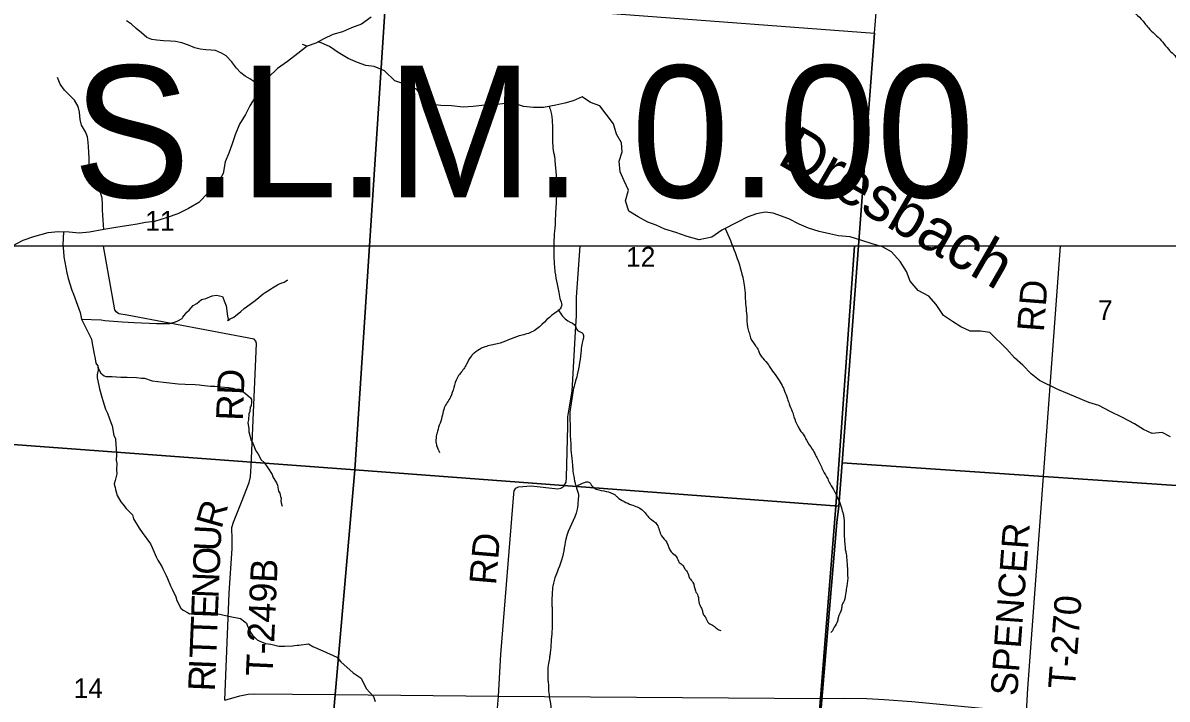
# Model space of a CAD drawing. Extents: x 0 to 42.5, y 0 to 22.
# Drawn here: x 4.279 to 5.494, y 14.597 to 15.314 of the extents above; entities that cross this region are included whole.
import ezdxf

# ---------------------------------------------------------------- set-up
doc = ezdxf.new("R2010")
doc.units = 0
for name, color, linetype in [('GM_X_Interchange_Ramps', 7, 'Continuous'), ('GM_X_Minor_River', 7, 'Continuous'), ('GM_X_Minor_River_Text', 7, 'Continuous'), ('GM_X_Section', 7, 'Continuous'), ('GM_X_Section_Text', 7, 'Continuous'), ('GM_X_State_Route', 7, 'Continuous'), ('GM_X_Township_Road', 7, 'Continuous'), ('GM_X_Township_Road_Text', 7, 'Continuous'), ('SH_Text', 7, 'Continuous')]:
    doc.layers.add(name, color=color, linetype=linetype)

msp = doc.modelspace()

# ---------------------------------------------------------------- linework, layer by layer
at = {"layer": 'GM_X_Interchange_Ramps'}
for points in [[(2.1, 14.1), (5.0849, 14.1), (5.0987, 14.2492), (5.1054, 14.3283), (5.1076, 14.3533), (5.1259, 14.5975), (5.1421, 14.8012), (5.162, 15.0772)], [(5.162, 15.0772), (5.1421, 14.8012), (5.1259, 14.5975), (5.1076, 14.3533), (5.1054, 14.3283), (5.0987, 14.2492), (5.0849, 14.1), (8.0699, 14.1)]]:
    msp.add_lwpolyline(points, dxfattribs=at)
at = {"layer": 'GM_X_Minor_River'}
for points in [[(4.649, 15.3203), (4.6387, 15.3128), (4.6281, 15.3091), (4.6186, 15.3046), (4.6083, 15.3017), (4.5988, 15.2972), (4.5901, 15.2927), (4.581, 15.2894), (4.576, 15.2911)], [(4.5335, 15.2469), (4.5264, 15.2505), (4.5203, 15.2547), (4.5152, 15.2575), (4.5105, 15.2613), (4.5059, 15.2663), (4.5008, 15.2731), (4.4949, 15.2792), (4.4902, 15.2821), (4.4837, 15.2848), (4.479, 15.2853), (4.4735, 15.2857), (4.4674, 15.2863), (4.4617, 15.2878), (4.4549, 15.2905), (4.4479, 15.293), (4.4412, 15.2943), (4.4359, 15.2949), (4.4287, 15.2953), (4.4213, 15.2957), (4.416, 15.2967), (4.411, 15.2986), (4.4051, 15.3037), (4.3995, 15.3081), (4.3945, 15.3129), (4.3894, 15.3165)], [(5.4974, 14.8748), (5.4888, 14.8794), (5.4782, 14.8783), (5.4687, 14.8826), (5.4593, 14.8887), (5.4465, 14.8953), (5.4333, 14.9018), (5.4213, 14.908), (5.4107, 14.9115), (5.388, 14.9208), (5.3779, 14.9251), (5.3583, 14.9347), (5.3496, 14.9416), (5.3406, 14.9508), (5.3319, 14.9588), (5.3237, 14.968), (5.3057, 14.9856), (5.2958, 14.9872), (5.2849, 14.9869), (5.2751, 14.9915), (5.266, 14.9973), (5.2566, 15.0038), (5.2487, 15.0153), (5.2409, 15.0241), (5.2296, 15.0302), (5.2213, 15.0402), (5.2172, 15.0504), (5.2105, 15.0611), (5.2015, 15.0714), (5.1917, 15.0764), (5.1808, 15.0796), (5.1698, 15.0834), (5.1573, 15.087), (5.1449, 15.0882), (5.1354, 15.0902), (5.1245, 15.0929), (5.1131, 15.0964), (5.1033, 15.1007), (5.0924, 15.1061), (5.0758, 15.1123), (5.0671, 15.1135), (5.058, 15.1117), (5.0481, 15.108), (5.0386, 15.1031), (5.0211, 15.0942), (5.0105, 15.0867), (4.9972, 15.0841), (4.9844, 15.0876), (4.9723, 15.0919), (4.9606, 15.0954), (4.9515, 15.0997), (4.9425, 15.1028), (4.9323, 15.1085), (4.9225, 15.1143), (4.9188, 15.1253), (4.9223, 15.1367), (4.9175, 15.1466), (4.9134, 15.1561), (4.9123, 15.1675), (4.9154, 15.1773), (4.9148, 15.1868), (4.9095, 15.196), (4.9062, 15.207), (4.8983, 15.2173), (4.8916, 15.2261), (4.8818, 15.2296), (4.8728, 15.2357), (4.8633, 15.2316), (4.8545, 15.2291), (4.8451, 15.2269), (4.8318, 15.2243), (4.8212, 15.2244), (4.8106, 15.2256), (4.8012, 15.2287), (4.7909, 15.2288), (4.7777, 15.2267), (4.7663, 15.2264), (4.7572, 15.2253), (4.7466, 15.2246), (4.7341, 15.2263), (4.7228, 15.2264), (4.7141, 15.2276), (4.7047, 15.2352), (4.6972, 15.244), (4.6836, 15.2494), (4.6742, 15.2526), (4.6633, 15.2633), (4.652, 15.2679), (4.6433, 15.2691), (4.6346, 15.2722), (4.6244, 15.2765), (4.6138, 15.2826), (4.6048, 15.2892), (4.5958, 15.293), (4.5925, 15.294)], [(4.581, 15.2894), (4.5713, 15.2816), (4.5603, 15.2733), (4.5496, 15.2658), (4.5396, 15.2564), (4.5335, 15.2469), (4.5262, 15.236), (4.52, 15.2261), (4.5154, 15.2171), (4.5092, 15.2068), (4.5046, 15.1955), (4.5019, 15.1868), (4.498, 15.1758), (4.4941, 15.1667), (4.4917, 15.1545), (4.4852, 15.1424), (4.476, 15.1338), (4.4661, 15.1236), (4.455, 15.1172), (4.4439, 15.1116), (4.4325, 15.1075), (4.4188, 15.1034), (4.4093, 15.1024), (4.4006, 15.1005), (4.3918, 15.0991), (4.38, 15.0973), (4.3652, 15.0951), (4.35, 15.0922), (4.339, 15.0912), (4.3283, 15.092), (4.317, 15.0925), (4.3056, 15.0914), (4.2907, 15.087), (4.2793, 15.0833), (4.2679, 15.0773)], [(4.3652, 15.0951), (4.3644, 15.1049), (4.364, 15.11), (4.3638, 15.1157), (4.3636, 15.1216), (4.3633, 15.1282), (4.3616, 15.1343), (4.3555, 15.141), (4.3513, 15.1461), (4.3502, 15.1522), (4.3498, 15.1569), (4.3496, 15.1626), (4.3495, 15.1701), (4.3493, 15.1769), (4.3489, 15.1826), (4.3486, 15.1875), (4.3478, 15.1932), (4.3457, 15.1986), (4.3414, 15.2058), (4.34, 15.2115), (4.3393, 15.2193), (4.338, 15.2256), (4.3342, 15.2322), (4.3236, 15.2429), (4.319, 15.2491), (4.316, 15.2562)], [(4.3222, 15.0923), (4.3218, 15.0787), (4.3225, 15.0718), (4.3228, 15.0658), (4.3258, 15.0488), (4.3273, 15.0429), (4.3311, 15.0304), (4.3329, 15.0264), (4.3401, 15.0069), (4.3414, 14.9999), (4.346, 14.9906), (4.352, 14.9784)], [(4.3414, 14.9999), (4.3625, 14.999), (4.3663, 14.9982), (4.3847, 14.9971), (4.3973, 14.9963), (4.4211, 14.9953), (4.4353, 14.9952), (4.4412, 14.9971), (4.4437, 14.998), (4.4485, 15.0005), (4.449, 15.002), (4.4532, 15.0073), (4.4557, 15.0092), (4.4601, 15.0143), (4.4639, 15.0163), (4.4689, 15.0208), (4.4735, 15.0218), (4.4803, 15.0246), (4.4847, 15.0251), (4.491, 15.0237), (4.4936, 15.0173), (4.4951, 15.0138), (4.4966, 15.0028), (4.497, 14.9999), (4.4979, 14.9984), (4.4966, 14.9984), (4.4992, 15.0003), (4.5031, 15.0018), (4.5105, 15.0078), (4.5141, 15.011), (4.5244, 15.0186), (4.5275, 15.021), (4.5343, 15.0265), (4.5363, 15.028), (4.542, 15.0317), (4.5441, 15.0331), (4.5496, 15.0361), (4.5523, 15.0376), (4.5567, 15.039), (4.5588, 15.0404), (4.5601, 15.0411), (4.5588, 15.0406)], [(4.352, 14.9784), (4.3529, 14.9741), (4.3534, 14.9703), (4.3551, 14.9625), (4.3557, 14.9599), (4.3568, 14.9532), (4.3573, 14.9519), (4.3587, 14.9504), (4.359, 14.9481), (4.3604, 14.9456), (4.3619, 14.9425), (4.3657, 14.9395), (4.3674, 14.9391), (4.374, 14.939), (4.3833, 14.9384), (4.3898, 14.9384), (4.3999, 14.9379), (4.405, 14.9373), (4.4083, 14.9371), (4.4166, 14.9342), (4.4284, 14.9328), (4.444, 14.931), (4.4516, 14.9307), (4.462, 14.9303), (4.4666, 14.93), (4.4687, 14.9298), (4.4784, 14.9288), (4.483, 14.9286), (4.489, 14.928), (4.4978, 14.9272), (4.4999, 14.927), (4.5023, 14.9264), (4.505, 14.9254), (4.5098, 14.9238), (4.5117, 14.9238), (4.5156, 14.9208), (4.5208, 14.9164), (4.5219, 14.9146), (4.5221, 14.912), (4.5217, 14.9078), (4.5205, 14.9065), (4.5203, 14.9019), (4.519, 14.8993), (4.5189, 14.8928), (4.518, 14.8902), (4.5191, 14.8833), (4.5191, 14.8803), (4.5215, 14.8711), (4.5232, 14.8681), (4.5264, 14.8601), (4.5287, 14.8574), (4.5321, 14.8505), (4.5355, 14.8477), (4.5393, 14.8421), (4.544, 14.8351), (4.5447, 14.8324), (4.5485, 14.8261), (4.5495, 14.8236), (4.5506, 14.8172), (4.5519, 14.8151), (4.5528, 14.8116), (4.5534, 14.8099), (4.553, 14.8067), (4.5534, 14.805), (4.5545, 14.8015)], [(4.3588, 14.9496), (4.359, 14.9456), (4.3581, 14.9412), (4.3582, 14.9376), (4.3599, 14.9293), (4.3605, 14.9258), (4.3631, 14.9169), (4.3642, 14.9136), (4.3668, 14.9041), (4.3691, 14.9001), (4.3725, 14.89), (4.3742, 14.8866), (4.3759, 14.8765), (4.3774, 14.8731), (4.3781, 14.8657), (4.3783, 14.8636), (4.3786, 14.856), (4.3784, 14.8501), (4.379, 14.8467), (4.3787, 14.8404), (4.3789, 14.8356), (4.3772, 14.8286), (4.3762, 14.8252), (4.3766, 14.8233), (4.3771, 14.821), (4.3775, 14.8189), (4.3788, 14.8153), (4.3794, 14.8126), (4.3833, 14.806), (4.3854, 14.8035), (4.3888, 14.7987), (4.3955, 14.792), (4.3968, 14.788), (4.4028, 14.7779), (4.406, 14.7733), (4.4149, 14.7615), (4.4164, 14.7575), (4.4209, 14.7474), (4.4226, 14.7441), (4.4266, 14.7373), (4.4279, 14.7348), (4.4313, 14.7277), (4.4326, 14.7247), (4.436, 14.7167), (4.4377, 14.7134), (4.4415, 14.705), (4.4428, 14.7014), (4.447, 14.6932), (4.4494, 14.6909), (4.4547, 14.688), (4.4561, 14.6871), (4.4629, 14.6876), (4.469, 14.6879), (4.4715, 14.6881), (4.4831, 14.6884), (4.4848, 14.6873), (4.4929, 14.6855), (4.4977, 14.6847), (4.5102, 14.682), (4.515, 14.6785), (4.5165, 14.6772), (4.5172, 14.6749), (4.5214, 14.6671), (4.5231, 14.6644), (4.528, 14.6596), (4.5307, 14.6581), (4.5368, 14.6557), (4.5423, 14.6549), (4.5508, 14.6528), (4.5571, 14.6526), (4.5656, 14.6531), (4.5704, 14.6538), (4.5721, 14.6538)], [(4.5721, 14.6538), (4.5826, 14.6552), (4.5871, 14.6524), (4.5978, 14.6477), (4.6125, 14.6412), (4.6168, 14.6362), (4.6299, 14.6243), (4.6382, 14.6189), (4.6436, 14.6079), (4.6515, 14.5993), (4.6533, 14.5941)]]:
    msp.add_lwpolyline(points, dxfattribs=at)
for points in [[(5.1453, 15.8029), (5.1667, 15.772), (5.1755, 15.7626), (5.1789, 15.7567), (5.1905, 15.7437), (5.1978, 15.7392), (5.2095, 15.7302), (5.2163, 15.7271), (5.2254, 15.7188), (5.2301, 15.715), (5.2365, 15.7043), (5.24, 15.7001), (5.2452, 15.687), (5.2484, 15.6812), (5.254, 15.6658), (5.2573, 15.6601), (5.2638, 15.6485), (5.2707, 15.632), (5.2716, 15.6257), (5.2783, 15.6061), (5.282, 15.5981), (5.29, 15.5767), (5.2976, 15.5631), (5.3004, 15.5538), (5.3102, 15.5302), (5.3171, 15.5201), (5.3294, 15.4927), (5.3382, 15.4824), (5.3537, 15.4565), (5.3634, 15.4467), (5.3793, 15.4213), (5.3889, 15.4119), (5.4042, 15.3892), (5.413, 15.3808), (5.4272, 15.3603), (5.4424, 15.3438), (5.4504, 15.3337), (5.4664, 15.3182), (5.474, 15.309), (5.4877, 15.2954), (5.4939, 15.2879), (5.5044, 15.2764), (5.5091, 15.269), (5.518, 15.2592), (5.5261, 15.2536), (5.5276, 15.25), (5.536, 15.2423), (5.5421, 15.2396), (5.5537, 15.2341), (5.5616, 15.2321), (5.5777, 15.2268), (5.5878, 15.2176), (5.5951, 15.2133), (5.6139, 15.1987), (5.6157, 15.1924), (5.6273, 15.1739), (5.6327, 15.1665), (5.6434, 15.1472), (5.6529, 15.138), (5.6561, 15.1327), (5.667, 15.1204), (5.6724, 15.1162), (5.6825, 15.1075), (5.6872, 15.1044), (5.697, 15.0964), (5.7015, 15.0933), (5.7103, 15.0856), (5.7146, 15.0825), (5.7225, 15.0739), (5.7276, 15.0702), (5.7353, 15.0622), (5.7396, 15.0593), (5.746, 15.0518), (5.7519, 15.0445), (5.7553, 15.0396), (5.7619, 15.0315), (5.7652, 15.0266), (5.7703, 15.0237)], [(4.8378, 15.2255), (4.839, 15.2225), (4.841, 15.2112), (4.8415, 15.2002), (4.8415, 15.1921), (4.8416, 15.1866), (4.8427, 15.1767), (4.8436, 15.1724), (4.8439, 15.1686), (4.8452, 15.1536), (4.8455, 15.1472), (4.8456, 15.1298), (4.8451, 15.1192), (4.8447, 15.113), (4.844, 15.0973), (4.8434, 15.0909), (4.8429, 15.0724), (4.843, 15.0656), (4.8441, 15.0499), (4.8464, 15.037), (4.8479, 15.03), (4.8493, 15.0218), (4.8506, 15.0178), (4.8512, 15.0148), (4.8508, 15.0129), (4.8476, 15.009), (4.8409, 15.004), (4.8189, 14.9859), (4.8062, 14.982), (4.783, 14.9736), (4.7697, 14.9704), (4.7661, 14.9689), (4.7583, 14.9636), (4.7557, 14.9613), (4.7503, 14.9519), (4.7473, 14.9471), (4.7402, 14.9373), (4.7331, 14.917), (4.7266, 14.9056), (4.7247, 14.8982), (4.7193, 14.8809), (4.7181, 14.8755), (4.7179, 14.8677), (4.7193, 14.8633), (4.7216, 14.8582)], [(5.0249, 15.0961), (5.0434, 15.0442), (5.045, 15.0357), (5.0467, 15.0135), (5.0476, 15.0035), (5.0485, 14.9914), (5.0501, 14.9857), (5.0516, 14.9798), (5.057, 14.9716), (5.0602, 14.9664), (5.0615, 14.9626), (5.0647, 14.9583), (5.0706, 14.9512), (5.0736, 14.9466), (5.0792, 14.9391), (5.082, 14.9348), (5.0861, 14.9277), (5.0878, 14.9235), (5.091, 14.9153), (5.0926, 14.91), (5.096, 14.9018), (5.0978, 14.896), (5.1017, 14.8868), (5.1041, 14.8823), (5.1086, 14.8761), (5.1111, 14.8712), (5.1172, 14.862), (5.1206, 14.8556), (5.1263, 14.8445), (5.1288, 14.839), (5.1336, 14.8302), (5.1362, 14.8249), (5.1409, 14.8169), (5.1433, 14.8118), (5.1468, 14.8038), (5.1481, 14.7996), (5.15, 14.7929), (5.1507, 14.7886), (5.1512, 14.7784), (5.1511, 14.7716), (5.1518, 14.7613), (5.1523, 14.7555), (5.1531, 14.7511), (5.154, 14.7428), (5.1546, 14.7326), (5.1548, 14.728), (5.154, 14.7163), (5.1528, 14.7099), (5.151, 14.7009), (5.1487, 14.6958), (5.1483, 14.6922), (5.1447, 14.6828), (5.1441, 14.6794), (5.1406, 14.6728), (5.1391, 14.67), (5.1368, 14.6668)], [(4.8478, 15.0093), (4.8579, 14.9979), (4.8659, 14.9923), (4.8672, 14.9887), (4.8723, 14.9856), (4.8736, 14.9846), (4.873, 14.9746), (4.8718, 14.9669), (4.8677, 14.9406), (4.8634, 14.9244), (4.862, 14.9152), (4.8598, 14.8967), (4.86, 14.8914), (4.8604, 14.8749), (4.8609, 14.8662), (4.8611, 14.8611), (4.8623, 14.849), (4.8628, 14.8428), (4.8632, 14.8388), (4.865, 14.8278), (4.8659, 14.8242), (4.8674, 14.8193), (4.8687, 14.8151), (4.8686, 14.8075), (4.8676, 14.7981), (4.8555, 14.7663), (4.8535, 14.7541), (4.8451, 14.7279), (4.8418, 14.7166), (4.8412, 14.7107), (4.8409, 14.6962), (4.841, 14.692), (4.8409, 14.6684), (4.8403, 14.6616), (4.84, 14.6569), (4.839, 14.6459), (4.8384, 14.6414), (4.8372, 14.6344), (4.8364, 14.6261), (4.8364, 14.6231), (4.8366, 14.6186), (4.8366, 14.6165), (4.8369, 14.614), (4.8372, 14.6074), (4.8381, 14.5991), (4.8392, 14.5921), (4.8418, 14.5793), (4.8442, 14.5738), (4.8451, 14.5706), (4.8479, 14.5634), (4.8499, 14.5601), (4.851, 14.5558), (4.8527, 14.5525), (4.8538, 14.5459), (4.8557, 14.541), (4.8573, 14.533), (4.8595, 14.5277), (4.8614, 14.5197), (4.8662, 14.5115), (4.8668, 14.5075), (4.8686, 14.5043), (4.8712, 14.5005), (4.8734, 14.4927), (4.8762, 14.4872), (4.8784, 14.4765), (4.8812, 14.4697), (4.8836, 14.4583), (4.8864, 14.4515), (4.8884, 14.4426), (4.8918, 14.4372), (4.8923, 14.4344), (4.897, 14.4269), (4.8973, 14.4241), (4.9012, 14.4157), (4.9046, 14.4113), (4.907, 14.4045), (4.9102, 14.4007), (4.9126, 14.3948), (4.9162, 14.3902), (4.9167, 14.3873), (4.9218, 14.381), (4.9223, 14.3786), (4.9268, 14.3717), (4.9311, 14.3677), (4.9347, 14.3621), (4.9375, 14.3587), (4.9418, 14.3539), (4.9438, 14.3508), (4.9476, 14.3455), (4.9498, 14.3419), (4.9543, 14.3352), (4.9565, 14.3314), (4.961, 14.3245), (4.9668, 14.3171), (4.9673, 14.3135), (4.9702, 14.3106), (4.9711, 14.3039)], [(4.8665, 14.8222), (4.8818, 14.8255), (4.8835, 14.8226), (4.888, 14.8195), (4.9079, 14.8132), (4.9104, 14.8109), (4.9254, 14.8028), (4.9367, 14.7973), (4.9446, 14.7887), (4.9523, 14.782), (4.9573, 14.7698), (4.9629, 14.7627), (4.9674, 14.7528), (4.9728, 14.7478), (4.9761, 14.7417), (4.9797, 14.7388), (4.9818, 14.7348), (4.9844, 14.7318), (4.987, 14.7251), (4.9905, 14.7205), (4.9931, 14.7116), (4.9959, 14.7063), (4.9972, 14.6979), (4.9996, 14.693), (5.0018, 14.6862), (5.0044, 14.6825), (5.0074, 14.6772), (5.0125, 14.6745), (5.0164, 14.671), (5.0202, 14.6694)]]:
    msp.add_spline(points, degree=3, dxfattribs=at)
at = {"layer": 'GM_X_Section'}
for points in [[(4.1437, 15.3814), (4.6645, 15.3424), (4.6315, 14.8399), (4.1061, 14.8789)], [(5.188, 15.3601), (5.6573, 15.3278), (5.6186, 14.8156), (5.149, 14.8472), (5.1833, 15.3031)], [(5.1833, 15.3031), (5.149, 14.8472), (5.1456, 14.8014), (4.6315, 14.8399), (4.6645, 15.3424)], [(4.1061, 14.8789), (4.6315, 14.8399), (4.6015, 14.4962), (4.591, 14.3476), (4.0702, 14.3893)], [(5.6186, 14.8156), (5.5806, 14.2995), (5.1051, 14.3325), (5.1432, 14.7839), (5.1456, 14.8014), (5.149, 14.8472)], [(5.1456, 14.8014), (5.1432, 14.7839), (5.1051, 14.3325), (5.1039, 14.3089), (4.591, 14.3476), (4.6015, 14.4962), (4.6315, 14.8399)]]:
    msp.add_lwpolyline(points, close=True, dxfattribs=at)
at = {"layer": 'GM_X_State_Route'}
msp.add_lwpolyline([(4.4938, 14.5956), (4.5095, 14.6001), (4.5183, 14.6019), (4.5254, 14.6023), (4.5656, 14.6019), (4.6111, 14.6014), (4.7841, 14.5997), (5.126, 14.5972), (5.1502, 14.5976), (5.1752, 14.5973), (5.1936, 14.5961), (5.223, 14.5939), (5.3051, 14.5864), (5.3447, 14.5826)], dxfattribs=at)
at = {"layer": 'GM_X_Township_Road'}
for points in [[(4.4938, 14.5956), (4.4984, 14.7091), (4.5015, 14.7564), (4.5015, 14.7659), (4.5012, 14.7787), (4.5027, 14.7842), (4.5113, 14.8055), (4.5194, 14.8266), (4.5208, 14.8325), (4.5216, 14.8437), (4.5273, 14.974), (4.5267, 14.9763), (4.5249, 14.9784), (4.3899, 15.0041), (4.381, 15.0054), (4.3784, 15.0076), (4.3767, 15.0097), (4.3647, 15.0772)], [(4.763, 14.3452), (4.7841, 14.5997), (4.7867, 14.6441), (4.8005, 14.8143), (4.8009, 14.8176), (4.8026, 14.8204), (4.8055, 14.8217), (4.8188, 14.823), (4.847, 14.8196), (4.8503, 14.8205), (4.8535, 14.8227), (4.856, 14.8269), (4.8563, 14.8316), (4.8576, 14.8863), (4.8578, 14.8961), (4.8594, 14.9066), (4.8625, 14.9234), (4.866, 14.9862), (4.8668, 15.0038), (4.8669, 15.023), (4.8707, 15.0772)], [(5.3447, 14.5826), (5.3462, 14.608), (5.3809, 15.0772)]]:
    msp.add_lwpolyline(points, dxfattribs=at)
at = {"layer": 'SH_Text'}
msp.add_lwpolyline([(4.2087, 15.5307), (5.9141, 15.5307), (5.9141, 15.0772), (4.2087, 15.0772)], close=True, dxfattribs=at)

# ---------------------------------------------------------------- texts
at = {"layer": 'GM_X_Minor_River_Text'}
msp.add_text('Dresbach', height=0.04735, rotation=329.9992, dxfattribs=at).set_placement((5.0784, 15.1657))
at = {"layer": 'GM_X_Section_Text'}
for s, height, p in [('11', 0.02093, (4.4092, 15.0937)), ('12', 0.02093, (4.9196, 15.0555)), ('7', 0.0209, (5.4206, 14.9989)), ('14', 0.02093, (4.3331, 14.5976))]:
    msp.add_text(s, height=height, rotation=0, dxfattribs=at).set_placement(p)
at = {"layer": 'GM_X_Township_Road_Text'}
for s, height, rotation, p in [('RD', 0.02841, 85.5622, (5.363, 14.9857)), ('RD', 0.02841, 87.5332, (4.5126, 14.8916)), ('R', 0.0284, 74.075, (4.49, 14.7763)), ('U', 0.0284, 87.2231, (4.489, 14.7531)), ('RD', 0.02841, 85.0719, (4.7814, 14.7171)), ('SPENCER', 0.02841, 85.7718, (5.3347, 14.5994)), ('O', 0.0284, 87.6788, (4.488, 14.7281)), ('T-249B', 0.02841, 87.3967, (4.5443, 14.6204)), ('N', 0.0284, 87.6769, (4.487, 14.7032)), ('E', 0.0284, 87.6679, (4.4861, 14.6819)), ('T-270', 0.02841, 85.7741, (5.3959, 14.6067)), ('T', 0.0284, 87.6765, (4.4853, 14.6607)), ('T', 0.0284, 87.6783, (4.4844, 14.6395)), ('R', 0.0284, 87.6732, (4.483, 14.6045)), ('I', 0.0284, 87.6732, (4.4839, 14.6278))]:
    msp.add_text(s, height=height, rotation=rotation, dxfattribs=at).set_placement(p)
at = {"layer": 'SH_Text'}
msp.add_text(' S.L.M. 0.00', height=0.14, dxfattribs=at).set_placement((4.2801, 15.1289))

doc.saveas('drawing.dxf')
